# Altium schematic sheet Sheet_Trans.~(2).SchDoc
size A4
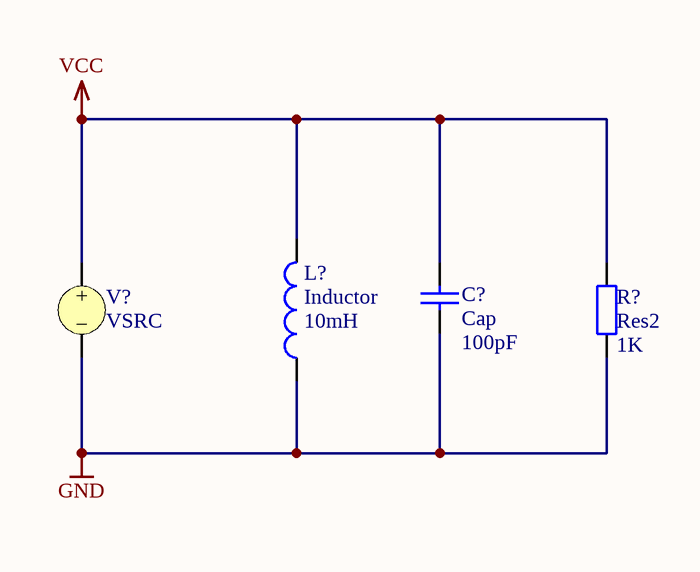
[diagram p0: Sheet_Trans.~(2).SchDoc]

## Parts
C?  Cap  value 100pF  [RAD-0.3]
L?  Inductor  value 10mH  [0402-A]
R?  Res2  value 1K  [AXIAL-0.4]
V?  VSRC

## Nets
GND: C?.1 L?.1 R?.1 V?.2
VCC: C?.2 L?.2 R?.2 V?.1

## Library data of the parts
C? = Cap: Capacitor
L? = Inductor: Code_IEC: 1005
R? = Res2: Resistor
V? = VSRC: Voltage Source; Note: PCB Footprint - Not required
